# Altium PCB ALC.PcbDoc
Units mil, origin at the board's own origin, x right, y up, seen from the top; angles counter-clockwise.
Board outline 6000 x 4000 mil, 2 copper layers (Top Layer, Bottom Layer); 20 components, 5 nets, 40 pads, 0 vias.
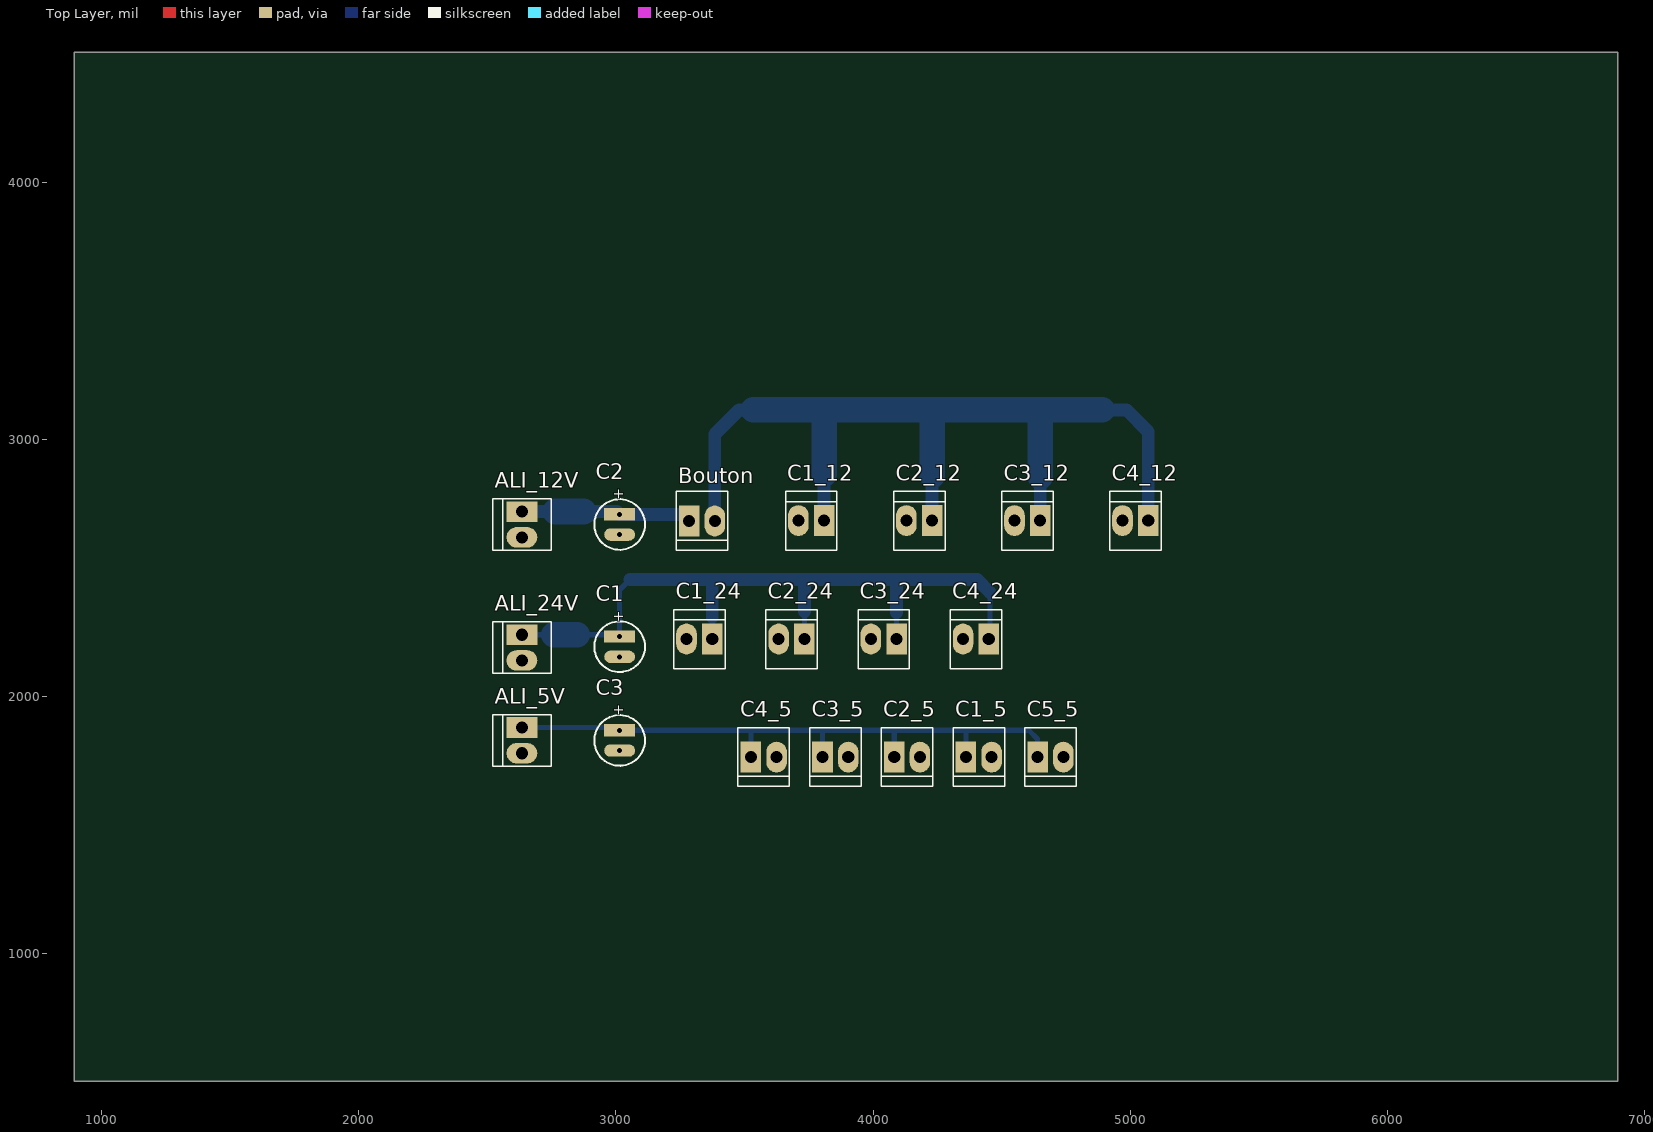
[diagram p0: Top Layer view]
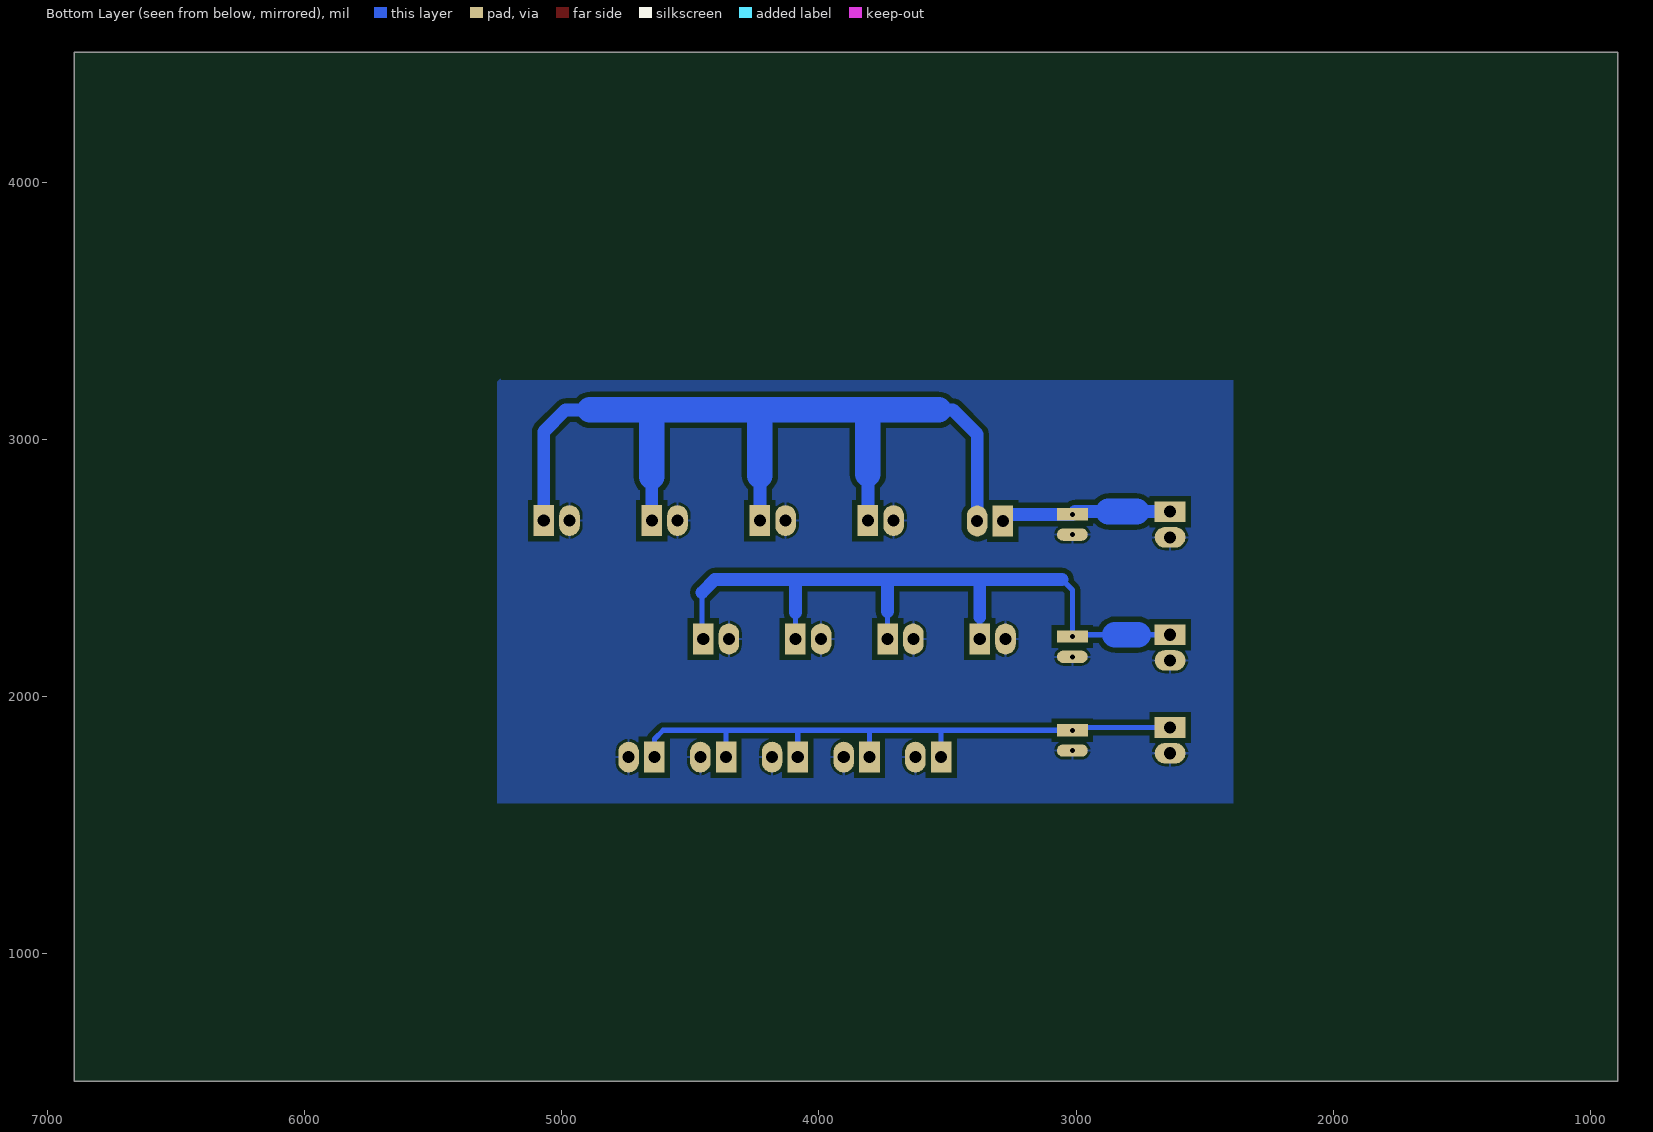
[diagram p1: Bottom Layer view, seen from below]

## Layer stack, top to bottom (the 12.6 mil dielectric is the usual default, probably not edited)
Top Solder: solder mask 0.4, Solder Resist, Dk 3.5
Top Layer: signal copper 1.4
Dielectric 1: dielectric 12.6, FR-4, Dk 4.8
Bottom Layer: signal copper 1.4
Bottom Solder: solder mask 0.4, Solder Resist, Dk 3.5

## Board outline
895,505 6895,505 6895,4505 895,4505

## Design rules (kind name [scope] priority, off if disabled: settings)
Clearance [All] p1: gap=20 ignorepadtopadclearanceinfootprint=FALSE
PolygonConnect [All] p1: connectstyle=Relief reliefconductorwidth=10 reliefentries=4 polygonreliefangle="90 Angle" airgapwidth=10
RoutingVias [All] p1: holewidth=28 width=50 viastyle="Through Hole" minholewidth=28 minwidth=50 maxholewidth=28 maxwidth=50
SolderMaskExpansion [All] p1: expansion=4
Width [All] p1: maxlimit=100 minlimit=20 preferedwidth=50
30 further rules are at their usual default settings.

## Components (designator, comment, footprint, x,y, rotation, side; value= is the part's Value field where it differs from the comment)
ALI_5V "Molex_2" Header_2Ecam 2635.79,1730 r90 top
ALI_12V "Molex_2" Header_2Ecam 2635.79,2569.51 r90 top
ALI_24V "Molex_2" Header_2Ecam 2635.79,2090.77 r90 top
Bouton "Molex_2" Header_2Ecam 3435,2683.68 r180 top
C1 "Cond pol radial" CAPPR2-5x6.8 3015,2233.74 r270 top
C1_5 "Molex_2" Header_2Ecam 4511.25,1765.79 r180 top
C1_12 "Molex_2" Header_2Ecam 3660,2683.68 r0 top
C1_24 "Molex_2" Header_2Ecam 3225,2223.6 r0 top
C2 "Cond pol radial" CAPPR2-5x6.8 3015,2708.74 r270 top
C2_5 "Molex_2" Header_2Ecam 4232.5,1765.79 r180 top
C2_12 "Molex_2" Header_2Ecam 4080,2683.68 r0 top
C2_24 "Molex_2" Header_2Ecam 3583.33,2223.6 r0 top
C3 "Cond pol radial" CAPPR2-5x6.8 3015,1869.23 r270 top
C3_5 "Molex_2" Header_2Ecam 3953.75,1765.79 r180 top
C3_12 "Molex_2" Header_2Ecam 4500,2683.68 r0 top
C3_24 "Molex_2" Header_2Ecam 3941.67,2223.6 r0 top
C4_5 "Molex_2" Header_2Ecam 3675,1765.79 r180 top
C4_12 "Molex_2" Header_2Ecam 4920,2683.68 r0 top
C4_24 "Molex_2" Header_2Ecam 4300,2223.6 r0 top
C5_5 "Molex_2" Header_2Ecam 4790,1765.79 r180 top

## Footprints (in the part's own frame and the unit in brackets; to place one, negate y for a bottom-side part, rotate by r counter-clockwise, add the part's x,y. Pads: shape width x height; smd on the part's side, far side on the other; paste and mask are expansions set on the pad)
CAPPR2-5x6.8 [mil] "Capacitor, Electrolytic, Radial; Body 5 x 6.8 mm (Dia.xH typ); Pin Spacing 2 mm (typ)"
  rect 48x120 hole 19.68: 1(0,0)
  oval 48x120 hole 19.68: 2(78.74,0)
  silkscreen extent -59,-98 138,98
Header_2Ecam [mil]
  rect 80x120 hole 46.85: 1(150,0.79)
  oval 80x120 hole 46.85: 2(50,0.79)
  silkscreen extent 0,-114 200,114

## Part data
ALI_5V ALI_12V ALI_24V Bouton C1_5 C1_12 C1_24 C2_5 C2_12 C2_24 C3_5 C3_12 C3_24 C4_5 C4_12 C4_24 C5_5: "Header, 2-pin"
C1 C2 C3: "Condensateur polatisé"

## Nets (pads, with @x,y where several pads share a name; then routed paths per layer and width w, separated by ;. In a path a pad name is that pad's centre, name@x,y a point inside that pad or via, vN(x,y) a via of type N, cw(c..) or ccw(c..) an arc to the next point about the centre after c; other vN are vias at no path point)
5V: ALI_5V.1 C1_5.1 C2_5.1 C3.1 C3_5.1 C4_5.1 C5_5.1 | length 2514.7
  Bottom Layer w20: ALI_5V.1 3004.23,1880 C3.1 3530,1869.23 ; C4_5.1 3525,1864.23 3530,1869.23 ; C3_5.1 3803.75,1867.98 3805,1869.23 ; C2_5.1 4082.5,1866.73 4080,1869.23 ; C1_5.1 4361.25,1867.98 4360,1869.23 ; C5_5.1 4640,1835 4605.77,1869.23 4360,1869.23 ; 3530,1869.23 3805,1869.23 ; 3805,1869.23 4080,1869.23 ; 4080,1869.23 4360,1869.23
12V: ALI_12V.1 Bouton.1 C2.1 | length 665.2
  Bottom Layer w50: ALI_12V.1 2764.51,2719.51 ; 2874.51,2719.51 3004.23,2719.51 C2.1 3259.15,2708.74 Bouton.1
  Bottom Layer w100: 2764.51,2719.51 2874.51,2719.51
24V: ALI_24V.1 C1.1 C1_24.1 C2_24.1 C3_24.1 C4_24.1 | length 2922.2
  Bottom Layer w20: ALI_24V.1 2759.23,2240.77 ; 2849.23,2240.77 3007.97,2240.77 C1.1 3015,2415 3055,2455 ; C1_24.1 3375,2310 ; C2_24.1 3733.33,2331.67 ; C3_24.1 4091.67,2326.67 ; C4_24.1 4455,2229.39 4455,2405
  Bottom Layer w50: 3055,2455 3370,2455 ; 3375,2310 3375,2450 3370,2455 ; 3733.33,2331.67 3733.33,2451.67 3730,2455 ; 4091.67,2326.67 4091.67,2448.33 4085,2455 ; 4455,2405 4405,2455 4085,2455 ; 3370,2455 3730,2455 ; 3730,2455 4085,2455
  Bottom Layer w100: 2759.23,2240.77 2849.23,2240.77
GND: ALI_5V.2 ALI_12V.2 ALI_24V.2 C1.2 C1_5.2 C1_12.2 C1_24.2 C2.2 C2_5.2 C2_12.2 C2_24.2 C3.2 C3_5.2 C3_12.2 C3_24.2 C4_5.2 C4_12.2 C4_24.2 C5_5.2
S_12V: Bouton.2 C1_12.1 C2_12.1 C3_12.1 C4_12.1 | length 3737.9
  Bottom Layer w50: Bouton.2 3385,3020 3480,3115 3535,3115 ; C1_12.1 3810,2865 ; C2_12.1 4230,2860 ; C3_12.1 4650,2855 ; 4890,3115 4985,3115 5070,3030 C4_12.1
  Bottom Layer w100: 3535,3115 3805,3115 ; 3810,2865 3810,3110 3805,3115 ; 4230,2860 4230,3110 4225,3115 ; 4650,2855 4650,3115 ; 4890,3115 4650,3115 ; 3805,3115 4225,3115 ; 4225,3115 4650,3115

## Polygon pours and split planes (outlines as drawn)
GND on Bottom Layer (solid, remove dead copper, pour order 0): 2390,3230 5235,3230 5240,3235 5250,3225 5250,1585 2390,1585

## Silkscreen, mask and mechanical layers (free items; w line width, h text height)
Mechanical 1:
  lines w10: 5245,1580 2390,1580 2390,3235 5240,3235 5250,3225 5250,1580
